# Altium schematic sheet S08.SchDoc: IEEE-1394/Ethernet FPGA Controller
size 381 x 254 mm; Revision: 3.2; SheetNumber: 8; SheetTotal: 10
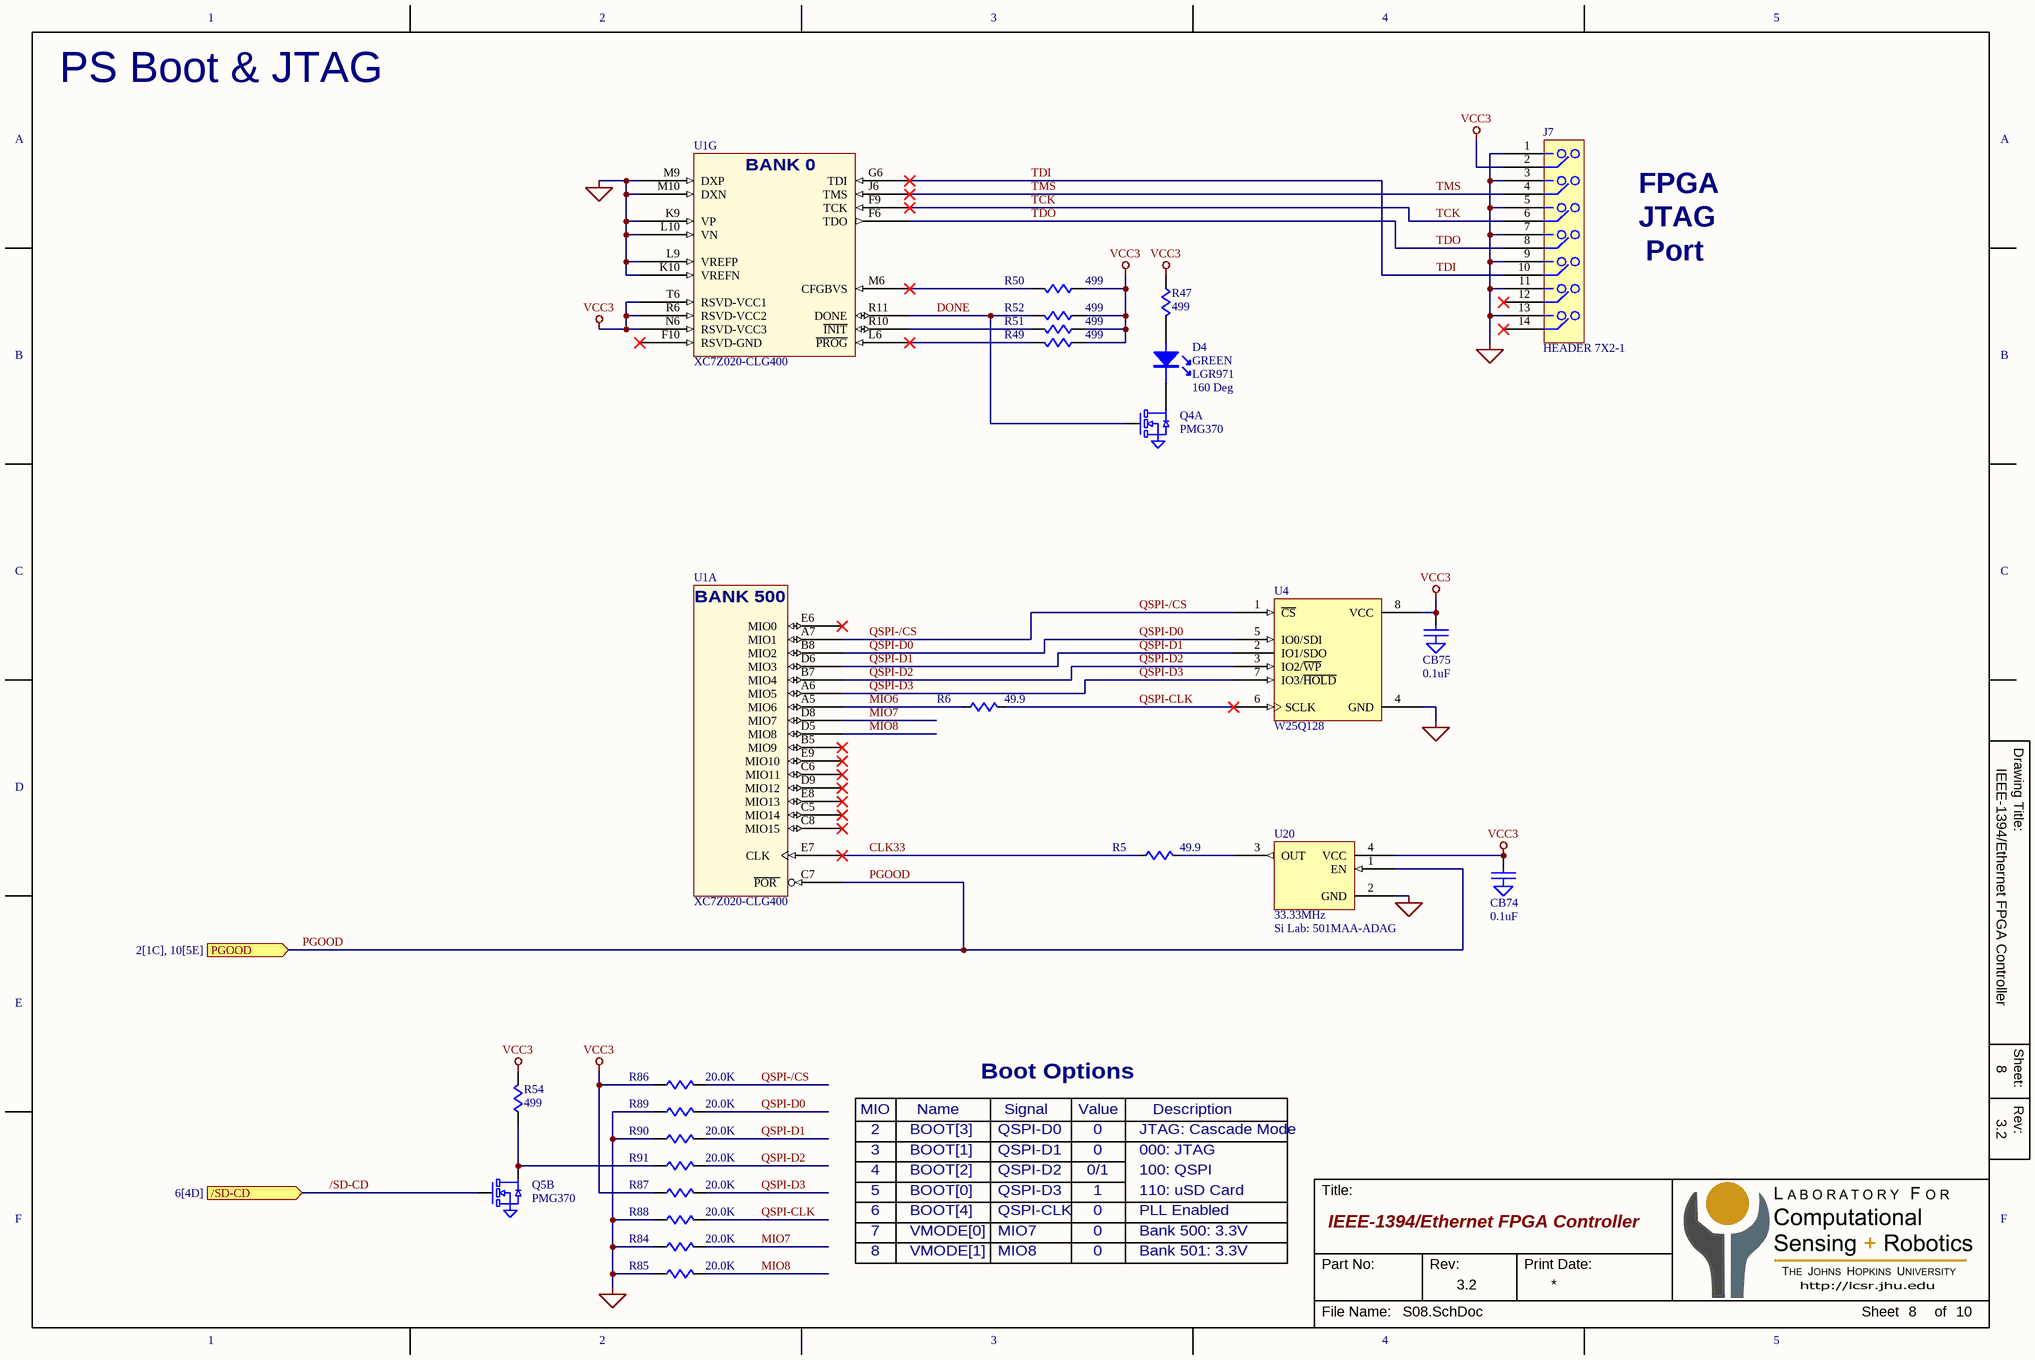
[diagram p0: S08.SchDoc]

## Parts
CB74  0.1uF  [C0201]
CB75  0.1uF  [C0201]
D4  Color: GREEN  P/N: LGR971  Angle: 160 Deg  [LED-0805]  (hidden comment: LED)
J7  HEADER 7X2-1  [HDR-7x2-2MM]
Q4  PMG370  [SC70-6-NP]  (part A of 2)
Q5  PMG370  [SC70-6-NP]  (part B of 2)
R5  49.9  [R0201]
R6  49.9  [R0201]
R47  499  [R0402]
R49  499  [R0402]
R50  499  [R0402]
R51  499  [R0402]
R52  499  [R0402]
R54  499  [R0402]
R84  20.0K  [R0402]
R85  20.0K  [R0402]
R86  20.0K  [R0402]
R87  20.0K  [R0402]
R88  20.0K  [R0402]
R89  20.0K  [R0402]
R90  20.0K  [R0402]
R91  20.0K  [R0402]
U1  XC7Z020-CLG400  [BGA-400-08mm]  (parts A,G of 9)
U4  W25Q128  [SOL-8]
U20  33.33MHz  [OSC-2x2.5mm]

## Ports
/SD-CD (in, see 6[4D]), PGOOD (in, see 2[1C], 10[5E])

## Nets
GND: CB74.2(GND) CB75.2(GND) J7.1 J7.3 J7.5 J7.7 J7.9 J7.11 J7.13 Q4.1(S1) Q5.4(S2) R84.1 R85.1 R88.1 R89.1 R90.1 U1.K9(VP) U1.K10(VREFN) U1.L9(VREFP) U1.L10(VN) U1.M9(DXP) U1.M10(DXN) U4.4(GND) U20.2(GND)
VCC3: CB74.1 CB75.1 J7.2 R47.1 R49.1 R50.1 R51.1 R52.1 R54.2 R86.1 R87.1 U1.N6(RSVD-VCC3) U1.R6(RSVD-VCC2) U1.T6(RSVD-VCC1) U4.8(VCC) U20.4(VCC)
/SD-CD: Q5.5(G2) ; port /SD-CD
CLK33: R5.1 U1.E7(CLK)
DONE: Q4.2(G1) R52.2 U1.R11(DONE)
MIO6: R6.1 U1.A5(MIO6)
MIO7: R84.2 U1.D8(MIO7)
MIO8: R85.2 U1.D5(MIO8)
PGOOD: U1.C7(~{POR_}) U20.1(EN) ; port PGOOD
QSPI-/CS: R86.2 U1.A7(MIO1) U4.1(~{CS})
QSPI-CLK: R6.2 R88.2 U4.6(SCLK)
QSPI-D0: R89.2 U1.B8(MIO2) U4.5(IO0/SDI)
QSPI-D1: R90.2 U1.D6(MIO3) U4.2(IO1/SDO)
QSPI-D2: R91.2 U1.B7(MIO4) U4.3(IO2/~{WP})
QSPI-D3: R87.2 U1.A6(MIO5) U4.7(IO3/~{HOLD})
TCK: J7.6 U1.F9(TCK)
TDI: J7.10 U1.G6(TDI)
TDO: J7.8 U1.F6(TDO)
TMS: J7.4 U1.J6(TMS)
NetD4_1: D4.1(C) Q4.6(D1)
NetD4_2: D4.2(A) R47.2
NetQ5_3: Q5.3(D2) R54.1 R91.1
NetR5_2: R5.2 U20.3(OUT)
NetR49_2: R49.2 U1.L6(~{PROG})
NetR50_2: R50.2 U1.M6(CFGBVS)
NetR51_2: R51.2 U1.R10(~{INIT})

Not connected (* = marked no-connect by the designer): J7 12* 14*; U1 B5(MIO9_)* C5(MIO14)* C6(MIO11)* C8(MIO15)* D9(MIO12)* E6(MIO0_)* E8(MIO13)* E9(MIO10)* F10(RSVD-GND)*

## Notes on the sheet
- PS Boot & JTAG
- FPGA
- JTAG
- Port
- MIO
- Name
- Signal
- Boot Options
- Value
- Description
- 2
- 3
- 4
- BOOT[3]
- BOOT[1]
- BOOT[2]
- QSPI-D0
- QSPI-D1
- QSPI-D2
- 0
- 0/1
- 100: QSPI
- JTAG: Cascade Mode
- 000: JTAG
- 5
- 6
- 7
- BOOT[0]
- BOOT[4]
- VMODE[0]
- QSPI-D3
- QSPI-CLK
- MIO7
- 1
- Bank 500: 3.3V
- 110: uSD Card
- PLL Enabled
- 8
- VMODE[1]
- MIO8
- Bank 501: 3.3V

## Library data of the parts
CB74 CB75 = CAP-GND
Q4 Q5 = MOSFET-N-DUAL6
R5 R6 R47 R49-R52 R54 R84-R91 = R
U20 = OSCILATOR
